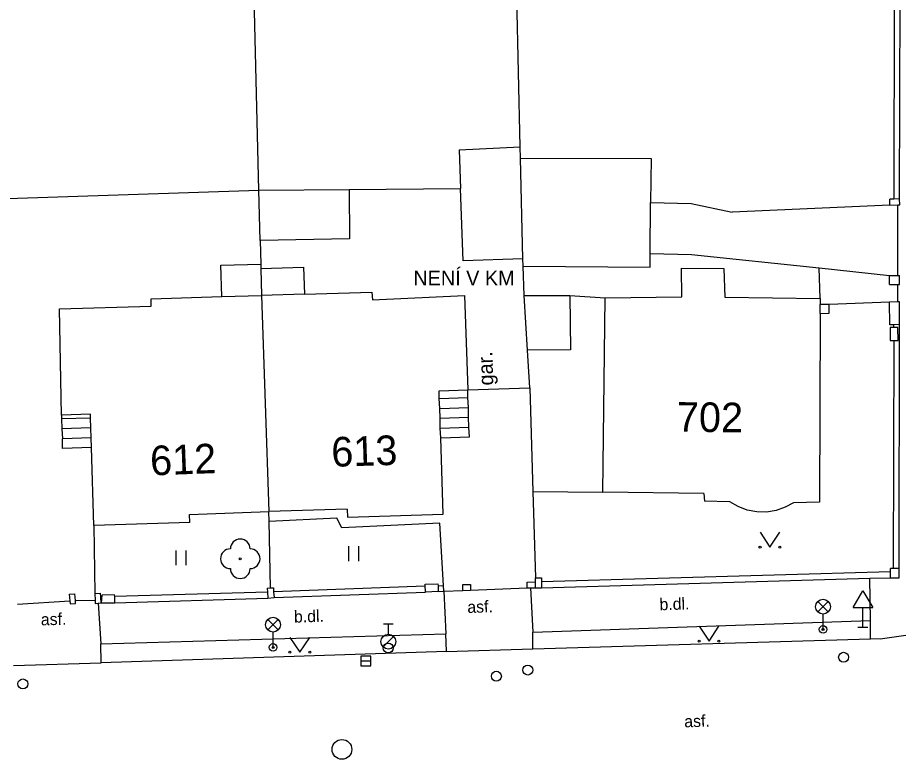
# Model space of a CAD drawing. Extents: x -642282 to -641982, y -1041678 to -1041427.
# Drawn here: x -642054.42 to -642009.58, y -1041503.26 to -1041465.69 of the extents above; entities that cross this region are included whole.
import ezdxf

# ---------------------------------------------------------------- set-up
doc = ezdxf.new("R2010")
doc.units = 0
for name, color, linetype in [('Budovy', 7, 'Continuous'), ('Ploty', 7, 'Continuous'), ('Popis objektů', 7, 'Continuous'), ('Popis povrchů', 7, 'Continuous'), ('Popis ČP_ ČE', 7, 'Continuous'), ('Popis-obec_pozn_', 7, 'Continuous'), ('Pris-HUP', 7, 'Continuous'), ('Rozhraní ploch 1', 7, 'Continuous'), ('Rozhraní ploch 2', 7, 'Continuous'), ('Vstup na pozemky', 7, 'Continuous'), ('Zeleň - stromy', 7, 'Continuous'), ('Znaky doprava', 7, 'Continuous'), ('Znaky kanalizace', 7, 'Continuous'), ('Znaky voda', 7, 'Continuous'), ('Značky doprava', 7, 'Continuous'), ('Značky KM', 7, 'Continuous')]:
    doc.layers.add(name, color=color, linetype=linetype)

msp = doc.modelspace()

# ---------------------------------------------------------------- linework, layer by layer
at = {"layer": 'Budovy'}
for p, q in [((-642032.06, -1041472.39), (-642028.97, -1041472.24)), ((-642028.96, -1041472.8), (-642028.97, -1041472.24)), ((-642032.06, -1041472.39), (-642031.99, -1041474.34)), ((-642028.84, -1041477.9), (-642028.96, -1041472.8)), ((-642028.96, -1041472.8), (-642022.35, -1041472.83)), ((-642022.35, -1041472.83), (-642022.37, -1041475.05)), ((-642042.21, -1041474.43), (-642037.64, -1041474.39)), ((-642042.14, -1041476.98), (-642042.21, -1041474.43)), ((-642037.64, -1041474.39), (-642037.62, -1041476.9)), ((-642031.86, -1041478.01), (-642031.99, -1041474.34)), ((-642022.39, -1041477.64), (-642022.37, -1041475.05)), ((-642037.62, -1041476.9), (-642042.14, -1041476.98)), ((-642028.84, -1041477.9), (-642031.86, -1041478.01)), ((-642028.83, -1041478.27), (-642028.84, -1041477.9)), ((-642022.4, -1041478.32), (-642022.39, -1041477.64)), ((-642044.14, -1041478.23), (-642042.11, -1041478.18)), ((-642044.09, -1041479.82), (-642044.14, -1041478.23)), ((-642042.11, -1041478.18), (-642042.11, -1041478.4)), ((-642042.11, -1041478.4), (-642039.94, -1041478.32)), ((-642042.11, -1041478.4), (-642042.07, -1041479.77)), ((-642039.94, -1041478.32), (-642039.9, -1041479.7)), ((-642028.83, -1041478.27), (-642022.4, -1041478.32)), ((-642020.79, -1041479.83), (-642020.81, -1041478.38)), ((-642020.81, -1041478.38), (-642018.66, -1041478.39)), ((-642018.66, -1041478.39), (-642018.62, -1041479.85)), ((-642047.67, -1041479.93), (-642044.09, -1041479.82)), ((-642044.09, -1041479.82), (-642042.07, -1041479.77)), ((-642039.9, -1041479.7), (-642042.07, -1041479.77)), ((-642042.07, -1041479.77), (-642041.7, -1041490.71)), ((-642039.9, -1041479.7), (-642036.48, -1041479.6)), ((-642036.48, -1041479.6), (-642036.46, -1041479.99)), ((-642036.46, -1041479.99), (-642031.8, -1041479.77)), ((-642031.8, -1041479.77), (-642031.63, -1041484.54)), ((-642028.78, -1041479.77), (-642026.46, -1041479.76)), ((-642028.609, -1041482.529), (-642028.78, -1041479.77)), ((-642026.46, -1041479.76), (-642026.43, -1041482.51)), ((-642024.67, -1041479.89), (-642020.79, -1041479.83)), ((-642018.62, -1041479.85), (-642013.78, -1041479.91)), ((-642052.31, -1041480.44), (-642047.66, -1041480.31)), ((-642047.66, -1041480.31), (-642047.67, -1041479.93)), ((-642024.79, -1041489.72), (-642024.67, -1041479.89)), ((-642013.78, -1041479.91), (-642013.78, -1041480.22)), ((-642013.78, -1041480.68), (-642013.78, -1041480.22)), ((-642052.2, -1041485.82), (-642052.31, -1041480.44)), ((-642013.78, -1041480.68), (-642013.82, -1041490.23)), ((-642026.43, -1041482.51), (-642028.609, -1041482.529)), ((-642028.49, -1041484.44), (-642028.609, -1041482.529)), ((-642033.08, -1041484.59), (-642031.63, -1041484.54)), ((-642033.07, -1041484.98), (-642033.08, -1041484.59)), ((-642031.63, -1041484.54), (-642028.49, -1041484.44)), ((-642033.05, -1041485.48), (-642033.07, -1041484.98)), ((-642033.03, -1041485.98), (-642033.05, -1041485.48)), ((-642050.74, -1041485.77), (-642052.2, -1041485.82)), ((-642050.74, -1041485.97), (-642050.74, -1041485.77)), ((-642050.72, -1041486.47), (-642050.74, -1041485.97)), ((-642033.02, -1041486.48), (-642033.03, -1041485.98)), ((-642050.7, -1041486.97), (-642050.72, -1041486.47)), ((-642033, -1041486.97), (-642033.02, -1041486.48)), ((-642050.69, -1041487.47), (-642050.7, -1041486.97)), ((-642032.87, -1041490.84), (-642033, -1041486.97)), ((-642050.56, -1041491.42), (-642050.69, -1041487.47)), ((-642019.67, -1041489.8), (-642024.79, -1041489.72)), ((-642019.67, -1041489.8), (-642019.64, -1041490.18)), ((-642018.38, -1041490.21), (-642019.64, -1041490.18)), ((-642037.732, -1041490.587), (-642041.7, -1041490.71)), ((-642037.732, -1041490.587), (-642037.72, -1041490.99)), ((-642018.36, -1041490.21), (-642018.38, -1041490.21)), ((-642017.94, -1041490.46), (-642018.36, -1041490.21)), ((-642017.48, -1041490.64), (-642017.94, -1041490.46)), ((-642017, -1041490.73), (-642017.48, -1041490.64)), ((-642015.56, -1041490.49), (-642016.02, -1041490.66)), ((-642015.13, -1041490.26), (-642015.56, -1041490.49)), ((-642013.82, -1041490.23), (-642015.13, -1041490.26)), ((-642045.724, -1041490.861), (-642041.7, -1041490.71)), ((-642045.71, -1041491.26), (-642045.724, -1041490.861)), ((-642037.72, -1041490.99), (-642032.87, -1041490.84)), ((-642016.5, -1041490.74), (-642017, -1041490.73)), ((-642016.02, -1041490.66), (-642016.5, -1041490.74)), ((-642045.71, -1041491.26), (-642050.56, -1041491.42))]:
    msp.add_line(p, q, dxfattribs=at)
at = {"layer": 'Ploty'}
for p, q in [((-642010, -1041453.7), (-642010.06, -1041474.88)), ((-642009.76, -1041474.87), (-642009.7, -1041453.71)), ((-642010.06, -1041481.389), (-642010.06, -1041481.242)), ((-642009.79, -1041493.6), (-642009.76, -1041481.24)), ((-642010.062, -1041482.039), (-642010.09, -1041493.6)), ((-642028.49, -1041484.44), (-642028.332, -1041489.701)), ((-642028.332, -1041489.701), (-642028.2, -1041494.07)), ((-642010.23, -1041493.76), (-642027.9, -1041494.27)), ((-642027.9, -1041494.57), (-642011.266, -1041494.09)), ((-642011.266, -1041494.09), (-642010.23, -1041494.06)), ((-642033.785, -1041494.489), (-642041.459, -1041494.77)), ((-642041.769, -1041494.79), (-642049.51, -1041495.019)), ((-642049.501, -1041495.338), (-642041.75, -1041495.09)), ((-642041.44, -1041495.07), (-642033.772, -1041494.789))]:
    msp.add_line(p, q, dxfattribs=at)
msp.add_lwpolyline([(-642041.627, -1041494.581), (-642041.69, -1041491.217), (-642041.7, -1041490.71)], dxfattribs=at)
at = {"layer": 'Pris-HUP'}
for p, q in [((-642010.26, -1041481.244), (-642010.27, -1041480.094)), ((-642009.76, -1041481.24), (-642009.77, -1041480.09))]:
    msp.add_line(p, q, dxfattribs=at)
for points in [[(-642009.77, -1041480.09), (-642009.85, -1041480.091), (-642010.27, -1041480.094)], [(-642009.76, -1041481.24), (-642010.06, -1041481.242), (-642010.26, -1041481.244)], [(-642010.06, -1041481.389), (-642010.246, -1041481.392), (-642010.237, -1041482.042), (-642010.062, -1041482.039), (-642009.837, -1041482.036), (-642009.846, -1041481.386), (-642010.06, -1041481.389)], [(-642033.79, -1041494.389), (-642033.141, -1041494.366), (-642033.136, -1041494.464), (-642033.122, -1041494.766), (-642033.772, -1041494.789), (-642033.774, -1041494.739), (-642033.785, -1041494.489), (-642033.79, -1041494.389)], [(-642049.501, -1041495.338), (-642049.51, -1041495.019), (-642049.513, -1041494.92), (-642050.163, -1041494.939), (-642050.19, -1041495.34), (-642049.501, -1041495.338)]]:
    msp.add_lwpolyline(points, dxfattribs=at)
at = {"layer": 'Rozhraní ploch 1'}
for p, q in [((-642013.33, -1041480.22), (-642013.78, -1041480.22)), ((-642010.27, -1041480.094), (-642013.33, -1041480.22)), ((-642031.62, -1041484.93), (-642031.63, -1041484.54)), ((-642033.07, -1041484.98), (-642031.62, -1041484.93)), ((-642031.6, -1041485.43), (-642031.62, -1041484.93)), ((-642033.05, -1041485.48), (-642031.6, -1041485.43)), ((-642031.59, -1041485.93), (-642031.6, -1041485.43)), ((-642052.2, -1041485.82), (-642052.2, -1041486.02)), ((-642050.74, -1041485.97), (-642052.2, -1041486.02)), ((-642052.2, -1041486.02), (-642052.18, -1041486.52)), ((-642033.03, -1041485.98), (-642031.59, -1041485.93)), ((-642031.57, -1041486.43), (-642031.59, -1041485.93)), ((-642050.72, -1041486.47), (-642052.18, -1041486.52)), ((-642052.18, -1041486.52), (-642052.16, -1041487.03)), ((-642033.02, -1041486.48), (-642031.57, -1041486.43)), ((-642050.7, -1041486.97), (-642052.16, -1041487.03)), ((-642038.26, -1041491.05), (-642041.69, -1041491.217)), ((-642050.56, -1041491.42), (-642050.523, -1041494.861)), ((-642028.34, -1041496.82), (-642011.24, -1041496.23)), ((-642011.23, -1041497.15), (-642011.24, -1041496.23)), ((-642050.21, -1041497.41), (-642032.74, -1041496.91)), ((-642032.71, -1041497.8), (-642032.74, -1041496.91)), ((-642028.34, -1041497.66), (-642028.34, -1041496.82)), ((-642028.34, -1041497.66), (-642011.23, -1041497.15)), ((-642010.75, -1041497.18), (-642011.23, -1041497.15)), ((-642009.451, -1041496.993), (-642010.75, -1041497.18)), ((-642050.19, -1041498.38), (-642050.21, -1041497.41)), ((-642032.71, -1041497.8), (-642050.19, -1041498.38)), ((-642032.71, -1041497.8), (-642028.34, -1041497.66)), ((-642054.64, -1041498.51), (-642050.19, -1041498.38))]:
    msp.add_line(p, q, dxfattribs=at)
for points in [[(-642013.78, -1041480.68), (-642013.33, -1041480.66), (-642013.33, -1041480.22)], [(-642033, -1041486.97), (-642031.55, -1041486.93), (-642031.57, -1041486.43)], [(-642050.69, -1041487.47), (-642052.15, -1041487.52), (-642052.16, -1041487.03)], [(-642032.855, -1041494.45), (-642033.04, -1041491.3), (-642038, -1041491.54), (-642038.26, -1041491.05)]]:
    msp.add_lwpolyline(points, dxfattribs=at)
at = {"layer": 'Rozhraní ploch 2'}
for p, q in [((-642042.21, -1041474.43), (-642042.77, -1041451.82)), ((-642028.97, -1041472.24), (-642029.42, -1041453.62)), ((-642055.49, -1041474.87), (-642042.21, -1041474.43)), ((-642037.64, -1041474.39), (-642031.99, -1041474.34)), ((-642010.25, -1041475.187), (-642010.26, -1041474.887)), ((-642009.75, -1041475.17), (-642009.76, -1041474.87)), ((-642022.37, -1041475.05), (-642020.32, -1041475.1)), ((-642020.32, -1041475.1), (-642018.24, -1041475.54)), ((-642010.25, -1041475.187), (-642018.24, -1041475.54)), ((-642042.14, -1041476.98), (-642042.11, -1041478.18)), ((-642022.39, -1041477.64), (-642020.3, -1041477.69)), ((-642020.3, -1041477.69), (-642013.84, -1041478.36)), ((-642028.78, -1041479.77), (-642028.83, -1041478.27)), ((-642013.78, -1041479.91), (-642013.84, -1041478.36)), ((-642013.84, -1041478.36), (-642010.27, -1041478.75)), ((-642010.27, -1041479.2), (-642010.27, -1041478.75)), ((-642009.77, -1041479.2), (-642009.77, -1041478.75)), ((-642026.46, -1041479.76), (-642024.67, -1041479.89)), ((-642028.332, -1041489.701), (-642024.79, -1041489.72)), ((-642009.79, -1041494.06), (-642009.79, -1041493.6)), ((-642028.2, -1041494.07), (-642027.9, -1041494.07)), ((-642011.24, -1041496.23), (-642011.266, -1041494.09)), ((-642010.23, -1041494.06), (-642009.79, -1041494.06)), ((-642033.136, -1041494.464), (-642032.855, -1041494.45)), ((-642032.84, -1041494.75), (-642032.855, -1041494.45)), ((-642031.888, -1041494.41), (-642031.498, -1041494.4)), ((-642031.88, -1041494.71), (-642031.888, -1041494.41)), ((-642031.498, -1041494.4), (-642031.49, -1041494.7)), ((-642028.627, -1041494.28), (-642028.2, -1041494.27)), ((-642028.62, -1041494.58), (-642028.627, -1041494.28)), ((-642028.457, -1041494.576), (-642028.34, -1041496.82)), ((-642028.2, -1041494.57), (-642027.9, -1041494.57)), ((-642051.806, -1041494.891), (-642051.526, -1041494.871)), ((-642050.523, -1041494.861), (-642050.223, -1041494.841)), ((-642041.75, -1041495.09), (-642041.44, -1041495.07)), ((-642033.122, -1041494.766), (-642032.84, -1041494.75)), ((-642032.84, -1041494.75), (-642032.74, -1041496.91)), ((-642031.88, -1041494.71), (-642031.49, -1041494.7)), ((-642051.77, -1041495.39), (-642051.49, -1041495.37)), ((-642050.347, -1041495.35), (-642050.21, -1041497.41))]:
    msp.add_line(p, q, dxfattribs=at)
for points in [[(-642009.76, -1041474.87), (-642010.06, -1041474.88), (-642010.26, -1041474.887)], [(-642010.25, -1041475.187), (-642009.86, -1041475.174), (-642009.75, -1041475.17)], [(-642010.27, -1041478.75), (-642009.86, -1041478.75), (-642009.77, -1041478.75)], [(-642010.27, -1041479.2), (-642009.85, -1041479.2), (-642009.77, -1041479.2)], [(-642010.23, -1041494.06), (-642010.23, -1041493.76), (-642010.23, -1041493.6)], [(-642009.79, -1041493.6), (-642010.09, -1041493.6), (-642010.23, -1041493.6)], [(-642028.2, -1041494.57), (-642028.2, -1041494.27), (-642028.2, -1041494.07)], [(-642027.9, -1041494.07), (-642027.9, -1041494.27), (-642027.9, -1041494.57)], [(-642041.782, -1041494.591), (-642041.627, -1041494.581), (-642041.472, -1041494.571)], [(-642041.782, -1041494.591), (-642041.769, -1041494.79), (-642041.75, -1041495.09)], [(-642041.472, -1041494.571), (-642041.459, -1041494.77), (-642041.44, -1041495.07)], [(-642028.62, -1041494.58), (-642028.457, -1041494.576), (-642028.2, -1041494.57)], [(-642051.806, -1041494.891), (-642051.781, -1041495.233), (-642051.77, -1041495.39)], [(-642051.49, -1041495.37), (-642051.501, -1041495.213), (-642051.526, -1041494.871)], [(-642050.523, -1041494.861), (-642050.5, -1041495.203), (-642050.49, -1041495.36)], [(-642050.19, -1041495.34), (-642050.21, -1041495.04), (-642050.223, -1041494.841)], [(-642050.49, -1041495.36), (-642050.347, -1041495.35), (-642050.19, -1041495.34)]]:
    msp.add_lwpolyline(points, dxfattribs=at)
at = {"layer": 'Vstup na pozemky'}
for p, q in [((-642009.86, -1041478.75), (-642009.86, -1041475.174)), ((-642009.85, -1041480.091), (-642009.85, -1041479.2)), ((-642031.49, -1041494.7), (-642028.62, -1041494.58)), ((-642032.84, -1041494.75), (-642031.88, -1041494.71)), ((-642054.432, -1041495.407), (-642051.781, -1041495.233)), ((-642051.501, -1041495.213), (-642050.5, -1041495.203))]:
    msp.add_line(p, q, dxfattribs=at)
at = {"layer": 'Zeleň - stromy'}
msp.add_circle((-642043.15, -1041493.1), 0.05, dxfattribs=at)
for centre, start, end in [((-642043.15, -1041492.6), 0, 180), ((-642043.65, -1041493.1), 90, 270), ((-642042.65, -1041493.1), 270, 90), ((-642043.15, -1041493.6), 180, 0)]:
    msp.add_arc(centre, 0.5, start, end, dxfattribs=at)
at = {"layer": 'Znaky doprava'}
for p, q in [((-642013.905, -1041495.265), (-642013.375, -1041495.795)), ((-642013.905, -1041495.795), (-642013.375, -1041495.265)), ((-642013.64, -1041496.68), (-642013.64, -1041495.905)), ((-642041.755, -1041496.175), (-642041.225, -1041496.705)), ((-642041.755, -1041496.705), (-642041.225, -1041496.175)), ((-642041.49, -1041497.59), (-642041.49, -1041496.815))]:
    msp.add_line(p, q, dxfattribs=at)
for centre, radius in [((-642013.64, -1041495.53), 0.375), ((-642041.49, -1041496.44), 0.375), ((-642013.64, -1041496.68), 0.19), ((-642013.64, -1041496.68), 0.05), ((-642041.49, -1041497.59), 0.19), ((-642041.49, -1041497.59), 0.05)]:
    msp.add_circle(centre, radius, dxfattribs=at)
at = {"layer": 'Znaky kanalizace'}
msp.add_line((-642037.04, -1041498.28), (-642036.54, -1041498.28), dxfattribs=at)
msp.add_lwpolyline([(-642037.04, -1041498.53), (-642036.54, -1041498.53), (-642036.54, -1041498.03), (-642037.04, -1041498.03)], close=True, dxfattribs=at)
msp.add_circle((-642038, -1041502.76), 0.5, dxfattribs=at)
at = {"layer": 'Znaky voda'}
for p, q in [((-642035.9, -1041496.4), (-642035.4, -1041496.4)), ((-642035.65, -1041496.925), (-642035.65, -1041496.4)), ((-642035.915, -1041497.565), (-642035.385, -1041497.035))]:
    msp.add_line(p, q, dxfattribs=at)
for centre, radius in [((-642035.65, -1041497.3), 0.375), ((-642035.66, -1041497.62), 0.25), ((-642012.6, -1041498.09), 0.25), ((-642028.59, -1041498.74), 0.25), ((-642030.18, -1041499.05), 0.25), ((-642054.16, -1041499.44), 0.25)]:
    msp.add_circle(centre, radius, dxfattribs=at)
at = {"layer": 'Značky doprava'}
for p, q in [((-642012.12, -1041495.57), (-642011.62, -1041494.72)), ((-642011.62, -1041494.72), (-642011.12, -1041495.57)), ((-642012.12, -1041495.57), (-642011.12, -1041495.57)), ((-642011.62, -1041496.57), (-642011.62, -1041495.57)), ((-642011.87, -1041496.57), (-642011.37, -1041496.57))]:
    msp.add_line(p, q, dxfattribs=at)
at = {"layer": 'Značky KM'}
for p, q in [((-642016.83, -1041491.76), (-642016.33, -1041492.51)), ((-642016.33, -1041492.51), (-642015.83, -1041491.76)), ((-642046.39, -1041493.43), (-642046.39, -1041492.68)), ((-642045.89, -1041493.43), (-642045.89, -1041492.68)), ((-642037.65, -1041493.22), (-642037.65, -1041492.47)), ((-642037.15, -1041493.22), (-642037.15, -1041492.47)), ((-642019.911, -1041496.52), (-642019.411, -1041497.27)), ((-642019.411, -1041497.27), (-642018.911, -1041496.52)), ((-642040.634, -1041497.088), (-642040.134, -1041497.838)), ((-642040.134, -1041497.838), (-642039.634, -1041497.088))]:
    msp.add_line(p, q, dxfattribs=at)
for centre in [(-642016.83, -1041492.51), (-642015.83, -1041492.51), (-642019.911, -1041497.27), (-642018.911, -1041497.27), (-642040.634, -1041497.838), (-642039.634, -1041497.838)]:
    msp.add_circle(centre, 0.05, dxfattribs=at)

# ---------------------------------------------------------------- texts
at = {"layer": 'Popis objektů'}
msp.add_text('gar.', height=0.75, rotation=91.872, dxfattribs=at).set_placement((-642030.33, -1041484.31))
at = {"layer": 'Popis povrchů'}
for s, rotation, p in [('b.dl.', 1.8434, (-642021.912, -1041495.713)), ('asf.', 1.6635, (-642031.645, -1041495.849)), ('asf.', 1.6635, (-642053.241, -1041496.478)), ('b.dl.', 1.8434, (-642040.422, -1041496.338)), ('asf.', 1.8171, (-642020.658, -1041501.644))]:
    msp.add_text(s, height=0.6, rotation=rotation, dxfattribs=at).set_placement(p)
at = {"layer": 'Popis ČP_ ČE'}
for s, rotation, p in [('702', 359.3996, (-642021.045, -1041486.663)), ('613', 1.7755, (-642038.519, -1041488.443)), ('612', 2.149, (-642047.689, -1041488.884))]:
    msp.add_text(s, height=1.5, rotation=rotation, dxfattribs=at).set_placement(p)
at = {"layer": 'Popis-obec_pozn_'}
msp.add_text('NENÍ V KM', height=0.75, dxfattribs=at).set_placement((-642034.384, -1041479.253))

doc.saveas('drawing.dxf')
